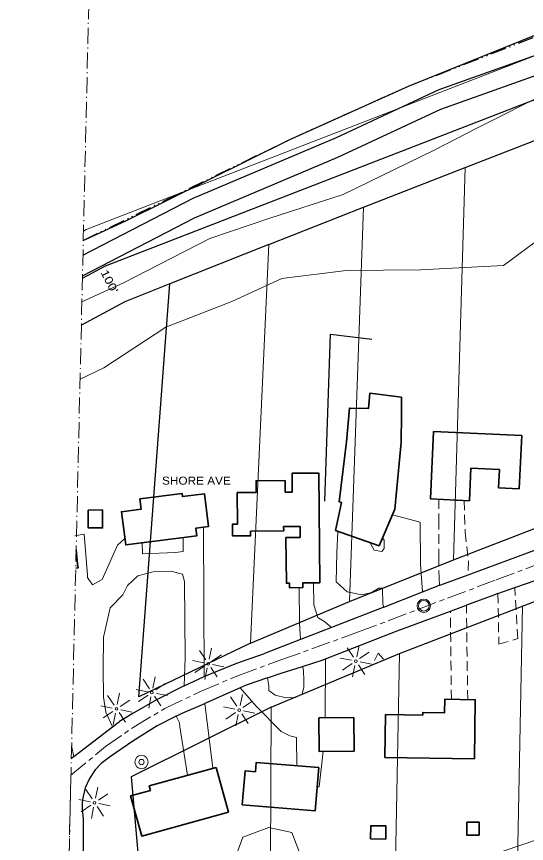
# Model space of a CAD drawing. Extents: x -861682 to -858969, y -1797841 to -1795153.
# Drawn here: x -861677 to -861295, y -1796083 to -1795463 of the extents above; entities that cross this region are included whole.
import ezdxf

# ---------------------------------------------------------------- set-up
doc = ezdxf.new("R2010")
doc.units = 0
doc.header["$LTSCALE"] = 2.4
for name, pattern in [('DASH_DOUBLE_DOT', [9.2, 5, -1.2, 0.3, -1.2, 0.3, -1.2]), ('DOT_DASHED', [7.7, 5, -1.2, 0.3, -1.2]), ('LONG_DASH_SHORT_DASH', [9.9, 6, -1.2, 1.5, -1.2]), ('MEDIUM_DASHED', [4.5, 3, -1.5])]:
    doc.linetypes.add(name, pattern=pattern)
for name, color, linetype, lineweight in [('10', 7, 'Continuous', 25), ('11', 7, 'Continuous', 13), ('12', 7, 'Continuous', 35), ('14', 7, 'Continuous', 25), ('16', 7, 'DASH_DOUBLE_DOT', 25), ('17', 7, 'Continuous', 13), ('18', 7, 'Continuous', 13), ('30', 7, 'Continuous', 13), ('31', 7, 'Continuous', 13), ('32', 7, 'LONG_DASH_SHORT_DASH', 13), ('36', 7, 'Continuous', 13), ('37', 7, 'Continuous', 13), ('42', 7, 'Continuous', 25), ('46', 7, 'Continuous', 13), ('6', 7, 'Continuous', 25), ('61', 7, 'Continuous', 13)]:
    doc.layers.add(name, color=color, linetype=linetype, lineweight=lineweight)
doc.layers.add('43', color=7, linetype='Continuous')

msp = doc.modelspace()

# ---------------------------------------------------------------- linework, layer by layer
at = {"layer": '10'}
for p, q in [((-861303.575, -1795891.243), (-861209.074, -1795857.778)), ((-861316.317, -1795895.756), (-861303.575, -1795891.243)), ((-861401.72, -1795905.836), (-861440.908, -1795921.108)), ((-861351.799, -1795908.884), (-861339.878, -1795904.456)), ((-861551.268, -1795964.857), (-861536.136, -1795958.002)), ((-861509.181, -1795966.458), (-861535.764, -1795978.069)), ((-861633.767, -1796017.879), (-861604.844, -1795995.621)), ((-861604.844, -1795995.621), (-861599.708, -1795991.669)), ((-861633.767, -1796017.879), (-861635.686, -1796019.478))]:
    msp.add_line(p, q, dxfattribs=at)
for points in [[(-861359.875, -1795889.53), (-861358.875, -1795889.14), (-861338.586, -1795881.647), (-861236.056, -1795843.783)], [(-861401.72, -1795905.836), (-861372.681, -1795894.519), (-861359.875, -1795889.53)], [(-861316.317, -1795895.756), (-861319.347, -1795896.829), (-861339.878, -1795904.456)], [(-861445.259, -1795944.757), (-861391.655, -1795923.689), (-861351.799, -1795908.884)], [(-861440.908, -1795921.108), (-861464.105, -1795930.148), (-861490.986, -1795940.624)], [(-861536.136, -1795958.002), (-861530.189, -1795955.309), (-861511.778, -1795947.932), (-861490.986, -1795940.624)], [(-861462.611, -1795950.367), (-861446.994, -1795945.439), (-861445.259, -1795944.757)], [(-861488.745, -1795958.943), (-861478.57, -1795955.403), (-861462.611, -1795950.367)], [(-861488.745, -1795958.943), (-861504.634, -1795964.473), (-861509.181, -1795966.458)], [(-861551.268, -1795964.857), (-861571.867, -1795975.398), (-861590.054, -1795985.77), (-861595.965, -1795989.371), (-861599.708, -1795991.669)], [(-861557.096, -1795987.696), (-861552.617, -1795985.429), (-861535.764, -1795978.069)], [(-861557.096, -1795987.696), (-861571.398, -1795994.934), (-861589.721, -1796006.272), (-861606.409, -1796017.746)], [(-861606.409, -1796017.746), (-861613.403, -1796023.09), (-861617.886, -1796027.941), (-861622.145, -1796034.361), (-861625.24, -1796041.417), (-861626.895, -1796047.812), (-861627.466, -1796052.181), (-861627.61, -1796055.483), (-861627.571, -1796057.687), (-861627.436, -1796059.739), (-861626.717, -1796064.684)], [(-861626.717, -1796064.684), (-861626.785, -1796084.061), (-861626.599, -1796105.326), (-861627.586, -1796127.546), (-861627.262, -1796164.642), (-861627.547, -1796186.147), (-861627.104, -1796209.773), (-861625.659, -1796266.943), (-861625.247, -1796314.198)]]:
    msp.add_lwpolyline(points, dxfattribs=at)
at = {"layer": '11'}
for p, q in [((-861536.729, -1795845.884), (-861536.136, -1795958.002)), ((-861631.827, -1795852.202), (-861633.108, -1795852.399)), ((-861445.577, -1795988.905), (-861445.259, -1795944.757)), ((-861529.667, -1796026.652), (-861535.764, -1795978.069)), ((-861635.461, -1796009.731), (-861635.461, -1796009.732)), ((-861635.461, -1796009.734), (-861635.461, -1796009.736)), ((-861635.461, -1796009.736), (-861633.767, -1796017.879))]:
    msp.add_line(p, q, dxfattribs=at)
at = {"layer": '11', "linetype": 'MEDIUM_DASHED'}
for p, q in [((-861351.077, -1795975.047), (-861351.799, -1795908.884)), ((-861338.853, -1795975.242), (-861339.878, -1795904.456))]:
    msp.add_line(p, q, dxfattribs=at)
for points in [[(-861360.373, -1795825.009), (-861360.482, -1795840.477), (-861360.481, -1795867.651), (-861360.334, -1795884.427), (-861359.875, -1795889.53)], [(-861341.473, -1795825.928), (-861340.788, -1795849.757), (-861338.238, -1795871.238), (-861338.586, -1795881.647)], [(-861316.317, -1795895.756), (-861315.481, -1795933.657), (-861301.339, -1795929.516), (-861303.575, -1795891.243)]]:
    msp.add_lwpolyline(points, dxfattribs=at)
at = {"layer": '11'}
for points in [[(-861395.209, -1795836.715), (-861374.408, -1795842.253), (-861374.131, -1795873.914), (-861372.681, -1795894.519)], [(-861595.573, -1795854.379), (-861601.102, -1795859.357), (-861612.69, -1795885.214), (-861619.746, -1795889.056), (-861623.574, -1795883.655), (-861623.588, -1795882.001), (-861625.983, -1795851.304), (-861631.827, -1795852.202)], [(-861552.002, -1795853.677), (-861551.911, -1795864.125), (-861557.575, -1795864.884), (-861582.376, -1795866.045), (-861582.536, -1795857.6)], [(-861436.062, -1795849.131), (-861436.825, -1795865.246), (-861437.344, -1795886.99), (-861429.008, -1795894.479), (-861418.119, -1795896.747), (-861410.809, -1795895.029), (-861405.403, -1795891.673), (-861402.568, -1795891.648), (-861402.463, -1795903.699), (-861401.72, -1795905.836)], [(-861411.931, -1795857.636), (-861408.961, -1795863.113), (-861403.28, -1795864.244), (-861401.41, -1795861.865), (-861401.464, -1795855.722), (-861402.63, -1795854.004)], [(-861551.268, -1795964.857), (-861550.504, -1795943.981), (-861551.006, -1795886.565), (-861552.471, -1795881.143), (-861561.234, -1795878.857), (-861574.461, -1795879.445), (-861585.778, -1795882.38), (-861593.511, -1795889.772), (-861597.231, -1795896.657), (-861606.598, -1795906.427), (-861611.604, -1795928.446), (-861611.87, -1795952.078), (-861611.684, -1795973.343), (-861609.931, -1795984.67), (-861604.844, -1795995.621)], [(-861464.953, -1795891.249), (-861464.72, -1795917.948), (-861464.105, -1795930.148)], [(-861454.351, -1795887.611), (-861454.207, -1795904.151), (-861451.053, -1795913.575), (-861445.826, -1795916.837), (-861440.908, -1795921.108)], [(-861488.745, -1795958.943), (-861487.703, -1795964.935), (-861487.672, -1795968.479), (-861483.151, -1795971.984), (-861474.865, -1795973.802), (-861467.777, -1795973.74), (-861462.838, -1795971.098), (-861461.466, -1795965.887), (-861461.525, -1795959.035), (-861461.795, -1795955.257), (-861461.813, -1795953.13), (-861462.611, -1795950.367)], [(-861466.857, -1796024.855), (-861467.044, -1796003.507), (-861472.016, -1796002.369), (-861478.661, -1795999.119), (-861497.258, -1795980.141), (-861509.181, -1795966.458)], [(-861548.694, -1796031.92), (-861554.543, -1795995.528), (-861554.568, -1795992.693), (-861557.096, -1795987.696)], [(-861635.461, -1796009.733), (-861635.461, -1796009.734), (-861635.461, -1796009.733)], [(-861451.616, -1796040.686), (-861450.179, -1796040.694), (-861447.108, -1796013.965)]]:
    msp.add_lwpolyline(points, dxfattribs=at)
at = {"layer": '12'}
for p, q in [((-861632.073, -1795862.863), (-861632.073, -1795862.864)), ((-861632.073, -1795862.866), (-861632.073, -1795862.868)), ((-861632.073, -1795862.868), (-861632.073, -1795862.87)), ((-861632.073, -1795862.87), (-861632.073, -1795862.873))]:
    msp.add_line(p, q, dxfattribs=at)
for points in [[(-861437.917, -1795848.478), (-861405.207, -1795860.007), (-861393.397, -1795832.494), (-861388.634, -1795782.594), (-861388.632, -1795782.83), (-861388.348, -1795761.324), (-861388.35, -1795761.088), (-861388.459, -1795748.565), (-861412.116, -1795745.464), (-861413.196, -1795757.052), (-861427.377, -1795756.703), (-861429.519, -1795782.005), (-861435.033, -1795826.95), (-861433.375, -1795827.408)], [(-861364.37, -1795774.111), (-861298.416, -1795777.316), (-861300.353, -1795817.176), (-861315.768, -1795816.427), (-861315.105, -1795802.791), (-861336.428, -1795801.754), (-861337.613, -1795826.116), (-861366.83, -1795824.695)], [(-861449.626, -1795887.569), (-861450.345, -1795805.345), (-861470.428, -1795805.521), (-861470.304, -1795819.697), (-861475.503, -1795819.742), (-861475.579, -1795811), (-861497.316, -1795811.189), (-861497.24, -1795819.932), (-861511.417, -1795820.055), (-861511.212, -1795843.684), (-861514.991, -1795843.717), (-861514.915, -1795852.459), (-861501.446, -1795852.342), (-861501.475, -1795849.034), (-861476.666, -1795848.817), (-861476.695, -1795845.509), (-861464.409, -1795845.401), (-861464.336, -1795853.671), (-861474.969, -1795853.765), (-861474.666, -1795888.024), (-861472.307, -1795888.003), (-861472.278, -1795891.313), (-861462.354, -1795891.226), (-861462.385, -1795887.682)], [(-861584.391, -1795824.711), (-861552.763, -1795820.653), (-861552.464, -1795822.98), (-861536.064, -1795820.873), (-861532.914, -1795845.394), (-861542.341, -1795846.605), (-861541.604, -1795852.341), (-861594.954, -1795859.196), (-861598.142, -1795834.383), (-861583.392, -1795832.488)], [(-861623.07, -1795833.083), (-861612.438, -1795832.99), (-861612.32, -1795846.457), (-861622.951, -1795846.551)], [(-861400.987, -1796018.524), (-861333.87, -1796019.592), (-861333.166, -1795975.332), (-861356.001, -1795974.969), (-861356.161, -1795985.045), (-861372.467, -1795984.786), (-861372.5, -1795986.857), (-861400.476, -1795986.412)], [(-861450.395, -1795988.947), (-861450.176, -1796013.992), (-861423.949, -1796013.763), (-861424.168, -1795988.718)], [(-861527.339, -1796026.008), (-861518.068, -1796059.481), (-861582.99, -1796077.463), (-861591.318, -1796047.396), (-861576.432, -1796043.273), (-861577.377, -1796039.86)], [(-861507.717, -1796054.192), (-861453.094, -1796058.677), (-861450.428, -1796026.204), (-861497.29, -1796022.357), (-861497.855, -1796029.244), (-861505.617, -1796028.607)], [(-861411.559, -1796079.581), (-861400.216, -1796079.718), (-861400.097, -1796069.88), (-861411.44, -1796069.743)], [(-861339.598, -1796067.137), (-861339.513, -1796076.825), (-861330.298, -1796076.744), (-861330.383, -1796067.056)]]:
    msp.add_lwpolyline(points, close=True, dxfattribs=at)
for points in [[(-861632.073, -1795862.873), (-861631.018, -1795873.557), (-861630.604, -1795876.55), (-861632.395, -1795876.798)], [(-861632.073, -1795862.865), (-861632.073, -1795862.866), (-861632.073, -1795862.865)]]:
    msp.add_lwpolyline(points, dxfattribs=at)
at = {"layer": '14'}
for points in [[(-861626.723, -1795630.941), (-861594.952, -1795616.402), (-861472.61, -1795555.55), (-861383.169, -1795515.308), (-861255.076, -1795463.683)], [(-861445.908, -1795826.337), (-861441.566, -1795701.299), (-861410.578, -1795705.045)]]:
    msp.add_lwpolyline(points, dxfattribs=at)
at = {"layer": '16'}
msp.add_lwpolyline([(-861626.723, -1795630.941), (-861472.61, -1795555.55), (-861383.169, -1795515.308), (-861255.062, -1795465.277), (-861255.091, -1795461.969), (-861252.757, -1795458.64), (-861246.18, -1795454.093), (-861224.544, -1795442.326), (-861215.594, -1795438.939), (-861193.906, -1795433.079), (-861174.372, -1795424.165), (-861166.595, -1795421.734), (-861151.552, -1795412.624), (-861140.246, -1795408.508), (-861130.583, -1795405.588), (-861111.007, -1795401.4), (-861092.36, -1795399.11), (-861089.058, -1795398.373), (-861073.286, -1795391.618), (-861053.05, -1795381.754), (-861024.784, -1795371.582), (-861009.693, -1795367.906), (-860990.816, -1795364.905), (-860980.662, -1795364.108)], dxfattribs=at)
at = {"layer": '17'}
for p, q in [((-861421.987, -1795943.048), (-861420.261, -1795934.648)), ((-861535.017, -1795945.418), (-861539.807, -1795938.29)), ((-861532.557, -1795944.958), (-861530.831, -1795936.558)), ((-861424.447, -1795943.508), (-861429.237, -1795936.38)), ((-861419.787, -1795944.448), (-861412.691, -1795939.708)), ((-861536.517, -1795947.618), (-861544.979, -1795945.944)), ((-861530.357, -1795946.358), (-861523.261, -1795941.618)), ((-861425.947, -1795945.708), (-861434.409, -1795944.034)), ((-861419.347, -1795946.968), (-861410.867, -1795948.692)), ((-861535.977, -1795950.118), (-861543.203, -1795954.974)), ((-861535.597, -1795960.078), (-861533.917, -1795951.478)), ((-861531.257, -1795951.018), (-861526.457, -1795958.232)), ((-861529.917, -1795948.878), (-861521.437, -1795950.602)), ((-861425.407, -1795948.208), (-861432.633, -1795953.064)), ((-861425.027, -1795958.168), (-861423.347, -1795949.568)), ((-861420.687, -1795949.108), (-861415.887, -1795956.322)), ((-861574.664, -1795966.593), (-861572.938, -1795958.193)), ((-861577.124, -1795967.053), (-861581.914, -1795959.925)), ((-861572.464, -1795967.993), (-861565.368, -1795963.253)), ((-861603.718, -1795979.336), (-861608.508, -1795972.208)), ((-861601.258, -1795978.876), (-861599.532, -1795970.476)), ((-861578.624, -1795969.253), (-861587.086, -1795967.579)), ((-861578.084, -1795971.753), (-861585.31, -1795976.609)), ((-861572.024, -1795970.513), (-861563.544, -1795972.237)), ((-861509.332, -1795979.728), (-861507.606, -1795971.328)), ((-861599.058, -1795980.276), (-861591.962, -1795975.536)), ((-861577.704, -1795981.713), (-861576.024, -1795973.113)), ((-861573.364, -1795972.653), (-861568.564, -1795979.867)), ((-861511.792, -1795980.188), (-861516.582, -1795973.06)), ((-861507.132, -1795981.128), (-861500.036, -1795976.388)), ((-861605.218, -1795981.536), (-861613.68, -1795979.862)), ((-861604.678, -1795984.036), (-861611.904, -1795988.892)), ((-861598.618, -1795982.796), (-861590.138, -1795984.52)), ((-861513.292, -1795982.388), (-861521.754, -1795980.714)), ((-861506.692, -1795983.648), (-861498.212, -1795985.372)), ((-861604.298, -1795993.996), (-861602.618, -1795985.396)), ((-861599.958, -1795984.936), (-861595.158, -1795992.15)), ((-861512.752, -1795984.888), (-861519.978, -1795989.744)), ((-861512.372, -1795994.848), (-861510.692, -1795986.248)), ((-861508.032, -1795985.788), (-861503.232, -1795993.002)), ((-861620.117, -1796049.66), (-861624.907, -1796042.532)), ((-861617.657, -1796049.2), (-861615.931, -1796040.8)), ((-861615.457, -1796050.6), (-861608.361, -1796045.86)), ((-861621.617, -1796051.86), (-861630.079, -1796050.186)), ((-861621.077, -1796054.36), (-861628.303, -1796059.216)), ((-861620.697, -1796064.32), (-861619.017, -1796055.72)), ((-861616.357, -1796055.26), (-861611.557, -1796062.474)), ((-861615.017, -1796053.12), (-861606.537, -1796054.844))]:
    msp.add_line(p, q, dxfattribs=at)
for centre in [(-861533.217, -1795948.318), (-861422.647, -1795946.408), (-861575.324, -1795969.953), (-861601.918, -1795982.236), (-861509.992, -1795983.088), (-861618.317, -1796052.56)]:
    msp.add_circle(centre, 1, dxfattribs=at)
at = {"layer": '18'}
for points in [[(-861627.784, -1795676.931), (-861596.674, -1795662.729), (-861531.982, -1795629.555), (-861487.69, -1795614.518), (-861432.082, -1795596.546), (-861364.083, -1795563.344), (-861330.912, -1795546.255), (-861278.234, -1795519.917), (-861241.977, -1795502.494), (-861200.029, -1795489.604), (-861135.894, -1795473.921), (-861059.793, -1795448.445), (-860986.512, -1795424.884), (-860905.443, -1795400.073), (-860827.906, -1795376.712), (-860758.776, -1795364.765), (-860677.115, -1795353.655), (-860512.688, -1795322.681), (-860272.176, -1795291.516), (-860031.805, -1795256.984)], [(-860948.091, -1795468.254), (-860994.524, -1795481.656), (-861034.298, -1795499.962), (-861074.762, -1795520.4), (-861165.551, -1795541.516), (-861169.101, -1795540.839), (-861216.106, -1795542.904), (-861230.925, -1795550.595), (-861261.315, -1795588.195), (-861282.472, -1795627.841), (-861312.053, -1795649.839), (-861374.171, -1795652.981), (-861429.932, -1795653.468), (-861478.083, -1795659.56), (-861515.504, -1795676.664), (-861564.957, -1795696), (-861611.242, -1795726.413), (-861629.124, -1795735.034)], [(-861516.5, -1796103.654), (-861507.27, -1796078.29), (-861487.721, -1796071.03), (-861470.438, -1796074.896), (-861462.699, -1796095.15)]]:
    msp.add_lwpolyline(points, dxfattribs=at)
at = {"layer": '30'}
for p, q in [((-861349.51, -1795870.472), (-861340.778, -1795576.325)), ((-861427.254, -1795901.556), (-861416.789, -1795606.124)), ((-861501.614, -1795932.996), (-861487.727, -1795634.171)), ((-861297.927, -1795905.066), (-861304.865, -1796260.285)), ((-861389.894, -1795940.687), (-861393.277, -1796116.269)), ((-861486.117, -1795980.981), (-861486.75, -1796148.044))]:
    msp.add_line(p, q, dxfattribs=at)
for points in [[(-861626.562, -1795623.983), (-861624.447, -1795622.863), (-860925.467, -1795351.444)], [(-861486.75, -1796148.044), (-861393.277, -1796116.269), (-861203.476, -1796051.939), (-861111.76, -1796021.472)]]:
    msp.add_lwpolyline(points, dxfattribs=at)
at = {"layer": '31'}
for radius in [5, 2]:
    msp.add_circle((-861583.14, -1796022.007), radius, dxfattribs=at)
at = {"layer": '32'}
for points in [[(-861635.972, -1796031.868), (-861610.028, -1796010.347), (-861588.712, -1795995.544), (-861565.619, -1795981.925), (-861538.381, -1795968.898), (-861510.551, -1795957.055), (-861477.984, -1795945.213), (-861420.547, -1795924.488), (-861317.516, -1795885.408), (-861160.601, -1795826.787), (-861110.862, -1795807.247), (-861056.978, -1795788.298), (-861002.502, -1795772.311), (-860944.474, -1795756.916), (-860841.147, -1795735.302), (-860618.21, -1795690.893), (-860377.808, -1795641.449), (-860358.046, -1795636.933), (-860342.059, -1795635.749), (-860328.736, -1795636.637), (-860314.229, -1795638.413), (-860299.425, -1795641.966), (-860286.694, -1795646.999), (-860274.26, -1795653.513)], [(-861635.972, -1796031.868), (-861668.34, -1797434.932), (-861671.877, -1797797.365)]]:
    msp.add_lwpolyline(points, dxfattribs=at)
at = {"layer": '36'}
for radius in [5, 4]:
    msp.add_circle((-861371.734, -1795904.848), radius, dxfattribs=at)
at = {"layer": '37'}
msp.add_lwpolyline([(-861408.54, -1795945.806), (-861405.923, -1795940.355), (-861401.816, -1795944.793)], dxfattribs=at)
at = {"layer": '42'}
for p, q in [((-861340.778, -1795576.325), (-861267.618, -1795547.889)), ((-861416.789, -1795606.124), (-861340.778, -1795576.325)), ((-861487.727, -1795634.171), (-861416.789, -1795606.124)), ((-861487.727, -1795634.171), (-861561.801, -1795663.66)), ((-861349.51, -1795870.472), (-861275.522, -1795841.812)), ((-861427.254, -1795901.556), (-861349.51, -1795870.472)), ((-861389.894, -1795940.687), (-861199.866, -1795867.084)), ((-861501.614, -1795932.996), (-861427.254, -1795901.556)), ((-861486.117, -1795980.981), (-861389.894, -1795940.687))]:
    msp.add_line(p, q, dxfattribs=at)
for points in [[(-861627.374, -1795659.18), (-861609.983, -1795649.976), (-860911.743, -1795378.903)], [(-861561.801, -1795663.66), (-861595.544, -1795677.135), (-861628.187, -1795694.412)], [(-861501.614, -1795932.996), (-861585.156, -1795973.247), (-861561.801, -1795663.66)], [(-861486.117, -1795980.981), (-861590.789, -1796033.063), (-861578.206, -1796177.971)]]:
    msp.add_lwpolyline(points, dxfattribs=at)
at = {"layer": '6'}
for points in [[(-861626.979, -1795642.068), (-861544.533, -1795599.421), (-861437.181, -1795553.823), (-861360.226, -1795517.943), (-861269.063, -1795485.483), (-861201.703, -1795460.32), (-861135.053, -1795434.926), (-860930.273, -1795370.755), (-860759.796, -1795329.096), (-860655.328, -1795305.026), (-860586.415, -1795295.208), (-860452.636, -1795272.3), (-860334.137, -1795258.505), (-859981.661, -1795225.976)], [(-861627.338, -1795657.588), (-861543.402, -1795614.17), (-861436.05, -1795568.572), (-861359.095, -1795532.692), (-861267.932, -1795500.232), (-861200.572, -1795475.069), (-861133.922, -1795449.675), (-860929.142, -1795385.504), (-860758.665, -1795343.845), (-860654.197, -1795319.775), (-860585.284, -1795309.957), (-860451.505, -1795287.049), (-860333.006, -1795273.254), (-859980.53, -1795240.725)]]:
    msp.add_lwpolyline(points, dxfattribs=at)
at = {"layer": '61', "linetype": 'DOT_DASHED'}
msp.add_line((-861615.801, -1795157.51), (-861676.699, -1797797.295), dxfattribs=at)

# ---------------------------------------------------------------- texts
at = {"layer": '43', "width": 1.25}
msp.add_text("100'", height=6, rotation=297.359, dxfattribs=at).set_placement((-861614.068, -1795654.856))
at = {"layer": '46', "width": 1.1}
msp.add_text('SHORE AVE', height=6, dxfattribs=at).set_placement((-861567.752, -1795814.072))

doc.saveas('drawing.dxf')
